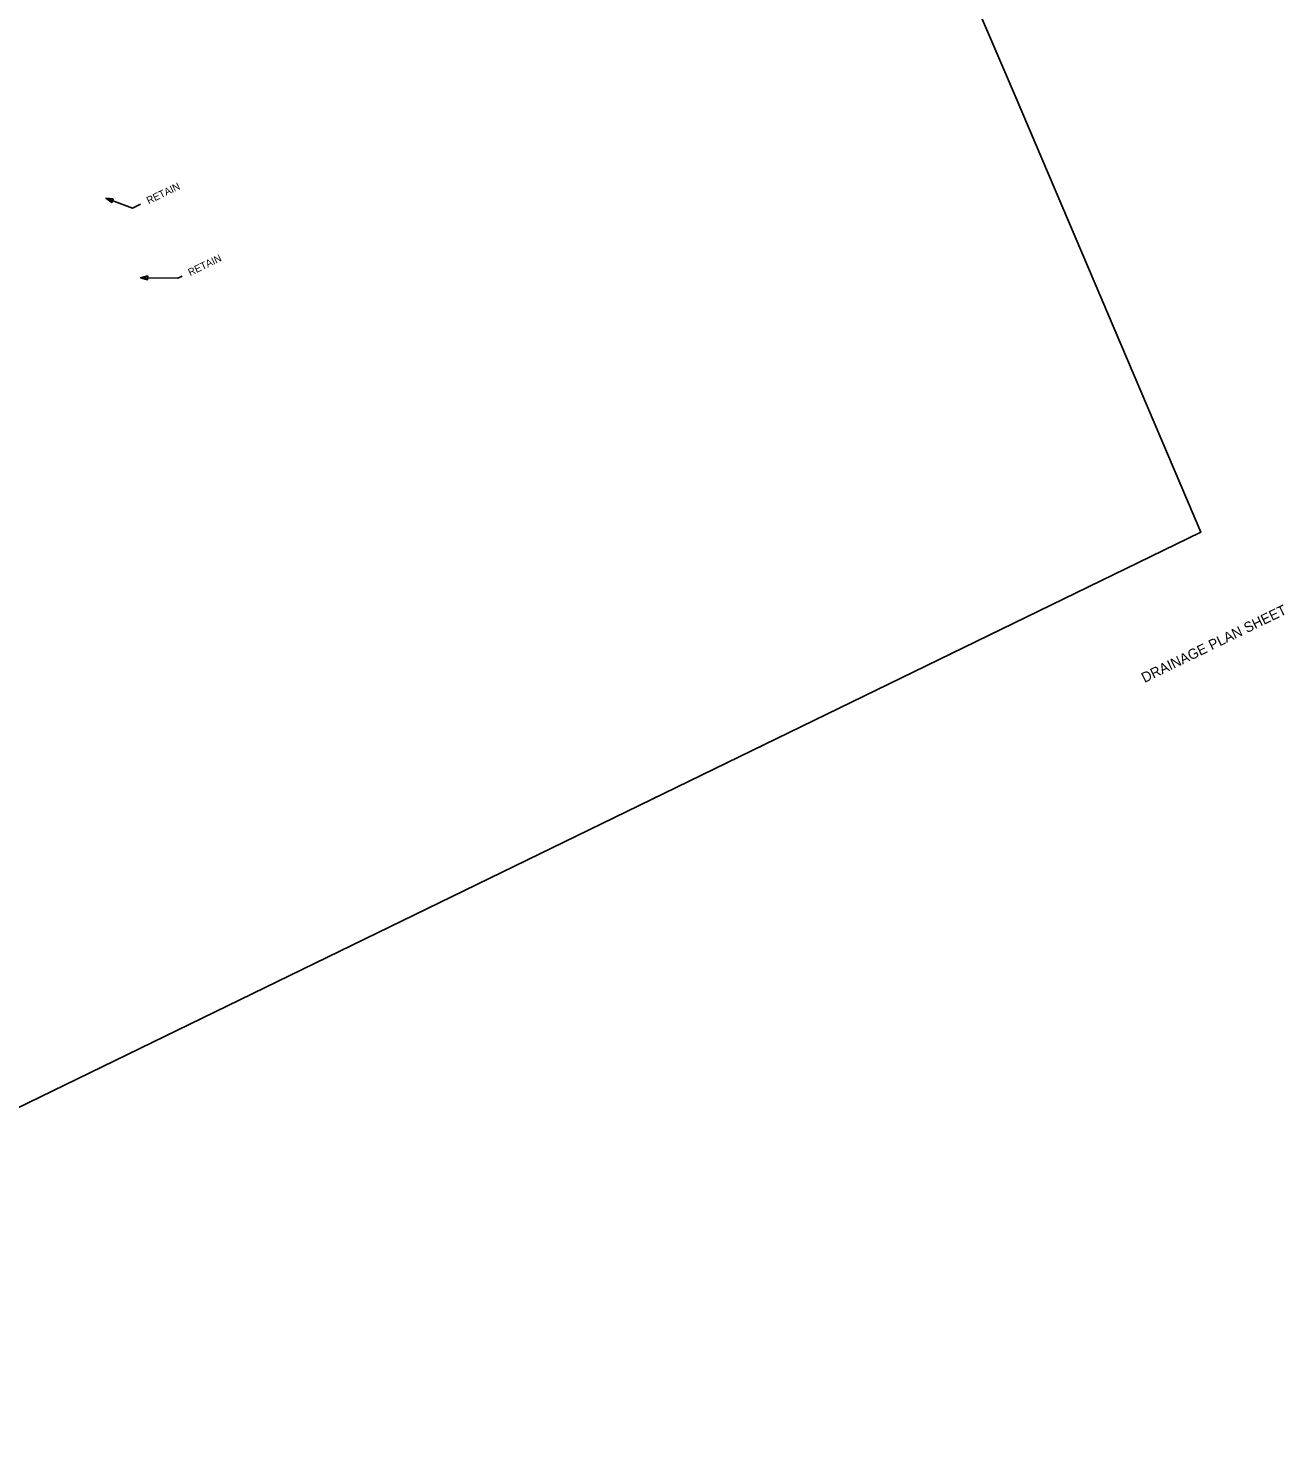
# Model space of a CAD drawing. Extents: x 1616914 to 1624709, y 1100483 to 1103157.
# Drawn here: x 1617894 to 1618758, y 1100558 to 1101540 of the extents above; entities that cross this region are included whole.
import ezdxf

# ---------------------------------------------------------------- set-up
doc = ezdxf.new("R2010")
doc.units = 0
for name, color, linetype in [('Level 2', 7, 'Continuous'), ('Level 20', 7, 'Continuous'), ('RFP', 7, 'Continuous')]:
    doc.layers.add(name, color=color, linetype=linetype)

msp = doc.modelspace()

# ---------------------------------------------------------------- linework, layer by layer
at = {"layer": 'Level 2'}
for points in [[(1617971.41, 1101419.45), (1617965.88, 1101416.76), (1617947.54, 1101423.61)], [(1617999.95, 1101370.01), (1617996.99, 1101368.57), (1617971.43, 1101368.87)]]:
    msp.add_lwpolyline(points, dxfattribs=at)
for points in [[(1617952.51, 1101423.14), (1617947.54, 1101423.61), (1617951.61, 1101420.71)], [(1617976.28, 1101370.11), (1617971.43, 1101368.87), (1617976.25, 1101367.52)]]:
    msp.add_lwpolyline(points, close=True, dxfattribs=at)
at = {"layer": 'RFP'}
msp.add_lwpolyline([(1617080.14, 1101099.03), (1617256.2, 1100856.12), (1617395.1, 1100558.35), (1618700.82, 1101193.66), (1618573.12, 1101494.1), (1618454.8, 1101769.78), (1618339.83, 1102037.66), (1618182.95, 1101960.1), (1618167.86, 1101990.6), (1616961.35, 1101407.95), (1616972.59, 1101384.68), (1616914.03, 1101356.41)], close=True, dxfattribs=at)
msp.add_lwpolyline([(1617080.14, 1101099.03), (1617256.2, 1100856.12), (1617395.1, 1100558.35), (1618700.82, 1101193.66), (1618573.12, 1101494.1), (1618454.8, 1101769.78), (1618339.83, 1102037.66), (1618182.95, 1101960.1), (1618167.86, 1101990.6), (1616961.35, 1101407.95), (1616972.59, 1101384.68), (1616914.03, 1101356.41)], close=True, dxfattribs=at)
msp.add_lwpolyline([(1617080.14, 1101099.03), (1617256.2, 1100856.12), (1617395.1, 1100558.35), (1618700.82, 1101193.66), (1618573.12, 1101494.1), (1618454.8, 1101769.78), (1618339.83, 1102037.66), (1618182.95, 1101960.1), (1618167.86, 1101990.6), (1616961.35, 1101407.95), (1616972.59, 1101384.68), (1616914.03, 1101356.41)], close=True, dxfattribs=at)
msp.add_lwpolyline([(1617080.14, 1101099.03), (1617256.2, 1100856.12), (1617395.1, 1100558.35), (1618700.82, 1101193.66), (1618573.12, 1101494.1), (1618454.8, 1101769.78), (1618339.83, 1102037.66), (1618182.95, 1101960.1), (1618167.86, 1101990.6), (1616961.35, 1101407.95), (1616972.59, 1101384.68), (1616914.03, 1101356.41)], close=True, dxfattribs=at)
msp.add_lwpolyline([(1617080.14, 1101099.03), (1617256.2, 1100856.12), (1617395.1, 1100558.35), (1618700.82, 1101193.66), (1618573.12, 1101494.1), (1618454.8, 1101769.78), (1618339.83, 1102037.66), (1618182.95, 1101960.1), (1618167.86, 1101990.6), (1616961.35, 1101407.95), (1616972.59, 1101384.68), (1616914.03, 1101356.41)], close=True, dxfattribs=at)

# ---------------------------------------------------------------- texts
at = {"layer": 'Level 2'}
for p in [(1617977, 1101419.39), (1618005.54, 1101369.95)]:
    msp.add_text('RETAIN', height=5, rotation=25.93046, dxfattribs=at).set_placement(p)
at = {"layer": 'Level 20'}
msp.add_text('DRAINAGE PLAN SHEET', height=6.9833, rotation=25.93046, dxfattribs=at).set_placement((1618662.17, 1101089.94))

doc.saveas('drawing.dxf')
